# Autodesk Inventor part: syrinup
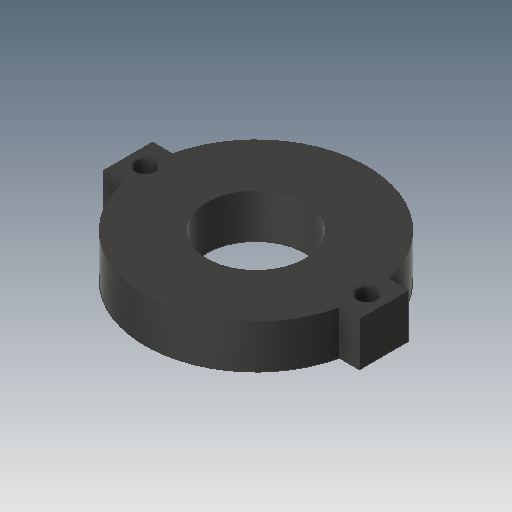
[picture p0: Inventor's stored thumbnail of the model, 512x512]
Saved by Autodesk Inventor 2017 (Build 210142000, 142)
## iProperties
Created: 2018-10
Part Number: syrinup
Material: Plastic, Opaque Black
Document SubType Name: Modeling
Designer: JK
Density: 0.952 g/cm^3
Appearance: Smooth - Black
Author: JK
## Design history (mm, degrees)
sketch "Sketch1"
  geometry: C1 r 10 at (0, 0); C2 r 22.5 at (0, 0); 1 further point
  constraints: 2 centre point, 2 coincident
  dimensions: "d0" = 20 diameter of C1; "d1" = 45 diameter of C2
extrude "Extrusion1" new body sketch "Sketch1" distance "d2" = 9; taper "d3" = 0 deg
sketch "Sketch2"
  geometry: L1 (-26, -5)-(-16, -5); L2 (-16, -5)-(-16, 5); L3 (-16, 5)-(-26, 5); L4 (-26, 5)-(-26, -5); L5 (16, -5)-(26, -5); L6 (26, -5)-(26, 5); L7 (26, 5)-(16, 5); L8 (16, 5)-(16, -5); C1 r 10 at (0, 0) reference; 1 further point
  constraints: 16 end point, 4 parallel, 3 collinear, 2 horizontal, 2 perpendicular
  dimensions: "d4" = 5 distance from line of point (0, 0) L1; "d5" = 10 distance of L3.end L1.start; "d6" = 10 distance of L2.end L3.end; "d25" = 16 distance from line of point (0, 0) L2; "d26" = 16 distance from line of L8 point (0, 0)
extrude "Extrusion2" join sketch "Sketch2" distance "d7" = 9; taper "d8" = 0 deg
sketch "Sketch5"
  geometry: L1 (-26, 3)-(-26, -3) reference; L2 (26, 5)-(26, -5) reference; C1 r 2 at (-22.5, 0); C2 r 2 at (22.5, 0); 1 further point
  constraints: 2 centre point
  dimensions: "d19" = 4 diameter of C1; "d20" = 3.5 distance from line of L1 C1.centre; "d21" = 3.5 distance from line of L2 C2.centre; "d22" = 4 diameter of C2
extrude "Extrusion5" cut sketch "Sketch5" distance "d23" = 41; taper "d24" = 0 deg
body "Solid1"
